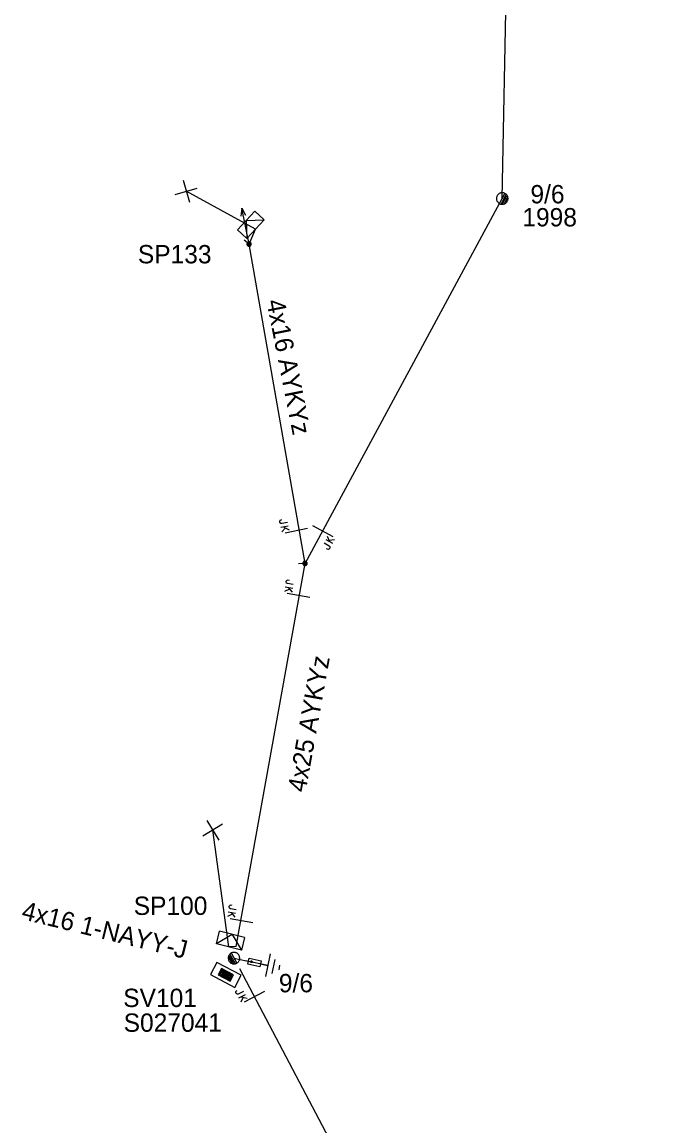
# Model space of a CAD drawing. Extents: x -788458 to -786145, y -1154772 to -1152372.
# Drawn here: x -786434.1 to -786399.7, y -1153357 to -1153296.8 of the extents above; entities that cross this region are included whole.
import ezdxf

# ---------------------------------------------------------------- set-up
doc = ezdxf.new("R2010")
doc.units = 0
for name, color, linetype in [('Vrstva 1', 7, 'Continuous'), ('Vrstva 12', 7, 'Continuous'), ('Vrstva 13', 7, 'Continuous'), ('Vrstva 14', 7, 'Continuous'), ('Vrstva 15', 7, 'Continuous'), ('Vrstva 16', 7, 'Continuous'), ('Vrstva 18', 7, 'Continuous'), ('Vrstva 2', 7, 'Continuous'), ('Vrstva 28', 7, 'Continuous'), ('Vrstva 29', 7, 'Continuous'), ('Vrstva 30', 7, 'Continuous'), ('Vrstva 31', 7, 'Continuous'), ('Vrstva 33', 7, 'Continuous'), ('Vrstva 34', 7, 'Continuous'), ('Vrstva 52', 7, 'Continuous'), ('Vrstva 53', 7, 'Continuous'), ('Vrstva 54', 7, 'Continuous'), ('Vrstva 55', 7, 'Continuous'), ('Vrstva 59', 7, 'Continuous'), ('Vrstva 8', 7, 'Continuous'), ('Vrstva 9', 7, 'Continuous')]:
    doc.layers.add(name, color=color, linetype=linetype)

# ---------------------------------------------------------------- blocks, each defined once
blk = doc.blocks.new('NN440')
at = {"layer": 'Vrstva 2'}
for points in [[(0.63, 0), (0.63, 0.06), (0.62, 0.13), (0.6, 0.19), (0.58, 0.25), (0.55, 0.31), (0.51, 0.37), (0.47, 0.42), (0.42, 0.46), (0.37, 0.51), (0.32, 0.54), (0.26, 0.57), (0.2, 0.59), (0.13, 0.61), (0.07, 0.62), (0, 0.63), (-0.06, 0.62), (-0.13, 0.61), (-0.19, 0.59), (-0.26, 0.57), (-0.31, 0.54), (-0.37, 0.51), (-0.42, 0.46), (-0.47, 0.42), (-0.51, 0.37), (-0.54, 0.31), (-0.57, 0.25), (-0.6, 0.19), (-0.62, 0.13), (-0.63, 0.06), (-0.63, 0), (-0.63, -0.07), (-0.62, -0.14), (-0.6, -0.2), (-0.57, -0.26), (-0.54, -0.32), (-0.51, -0.37), (-0.47, -0.43), (-0.42, -0.47), (-0.37, -0.51), (-0.31, -0.55), (-0.26, -0.58), (-0.19, -0.6), (-0.13, -0.62), (-0.06, -0.63), (0, -0.63), (0.07, -0.63), (0.13, -0.62), (0.2, -0.6), (0.26, -0.58), (0.32, -0.55), (0.37, -0.51), (0.42, -0.47), (0.47, -0.43), (0.51, -0.37), (0.55, -0.32), (0.58, -0.26), (0.6, -0.2), (0.62, -0.14), (0.63, -0.07), (0.63, 0)], [(-0.63, 0), (0.63, 0)], [(-0.6, -0.18), (0.57, -0.18)], [(-0.51, -0.32), (0.5, -0.32)], [(-0.37, -0.47), (0.35, -0.47)]]:
    blk.add_lwpolyline(points, dxfattribs=at)
blk = doc.blocks.new('NN560')
at = {"layer": 'Vrstva 2'}
for points in [[(1.999, -0.001), (1.59, 0.141)], [(0, -0.001), (1.999, -0.001)], [(1.999, -0.001), (1.59, -0.134)]]:
    blk.add_lwpolyline(points, dxfattribs=at)
blk = doc.blocks.new('NN840')
at = {"layer": 'Vrstva 15'}
for points in [[(0.003, 0.619), (0.003, -0.631)], [(-0.538, -0.385), (-0.538, -0.71)], [(-0.332, -0.385), (-0.332, -0.798)], [(-0.332, -0.641), (-0.125, -0.385)], [(-0.263, -0.557), (-0.091, -0.798)], [(-0.745, -0.71), (-0.745, -0.66)], [(-0.73, -0.764), (-0.745, -0.71)], [(-0.657, -0.798), (-0.73, -0.764)], [(-0.627, -0.798), (-0.657, -0.798)], [(-0.558, -0.764), (-0.627, -0.798)], [(-0.538, -0.71), (-0.558, -0.764)]]:
    blk.add_lwpolyline(points, dxfattribs=at)
blk = doc.blocks.new('NN800')
at = {"layer": 'Vrstva 1'}
for points in [[(-0.442, 0.442), (0.442, -0.442)], [(-0.442, -0.442), (0.442, 0.442)]]:
    blk.add_lwpolyline(points, dxfattribs=at)
blk = doc.blocks.new('NN820')
at = {"layer": 'Vrstva 13'}
for points in [[(-0.003, 0.004), (-0.003, -1.049)], [(-0.165, -0.813), (0.165, -0.813)], [(-0.165, -1.473), (-0.165, -0.813)], [(-0.003, -1.049), (-0.062, -0.926)], [(-0.003, -1.049), (0.057, -0.926)], [(0.165, -0.813), (0.165, -1.473)], [(0.165, -1.473), (-0.165, -1.473)], [(-0.003, -1.473), (-0.003, -1.871)]]:
    blk.add_lwpolyline(points, dxfattribs=at)
blk = doc.blocks.new('NN620')
at = {"layer": 'Vrstva 8'}
for points in [[(0.752, 0.004), (-0.748, 0.004)], [(-0.748, 0.004), (-0.748, -0.746)], [(0.752, -0.746), (0.752, 0.004)], [(0.368, -0.18), (-0.376, -0.18)], [(-0.376, -0.18), (-0.376, -0.558)], [(-0.376, -0.558), (0.368, -0.558)], [(0.321, -0.227), (-0.329, -0.227)], [(-0.329, -0.227), (-0.329, -0.51)], [(-0.329, -0.51), (0.321, -0.51)], [(0.274, -0.274), (-0.281, -0.274)], [(-0.281, -0.274), (-0.281, -0.463)], [(-0.281, -0.463), (0.274, -0.463)], [(0.227, -0.321), (-0.234, -0.321)], [(-0.234, -0.321), (-0.234, -0.416)], [(-0.234, -0.416), (0.227, -0.416)], [(-0.193, -0.369), (0.185, -0.369)], [(0.227, -0.416), (0.227, -0.321)], [(0.274, -0.463), (0.274, -0.274)], [(0.321, -0.51), (0.321, -0.227)], [(0.368, -0.558), (0.368, -0.18)], [(-0.748, -0.746), (0.752, -0.746)]]:
    blk.add_lwpolyline(points, dxfattribs=at)
blk = doc.blocks.new('NN630')
at = {"layer": 'Vrstva 9'}
for points in [[(-0.003, -0.7), (-0.703, 0)], [(-0.703, -0.7), (-0.703, 0), (0.697, 0), (0.697, -0.7)], [(-0.003, -0.7), (0.697, 0)], [(-0.703, -0.7), (0.697, -0.7)]]:
    blk.add_lwpolyline(points, dxfattribs=at)
blk = doc.blocks.new('NN810')
at = {"layer": 'Vrstva 14'}
for points in [[(0.004, -0.64), (0.004, -1.89)], [(0.629, -1.89), (-0.621, -1.89)], [(0.388, -2.2), (-0.399, -2.2)], [(0.004, -2.515), (-0.124, -2.515)], [(0.137, -2.515), (0.004, -2.515)]]:
    blk.add_lwpolyline(points, dxfattribs=at)
blk = doc.blocks.new('NN500')
at = {"layer": 'Vrstva 2'}
for points in [[(0, -0.24), (0.02, -0.23), (0.05, -0.23), (0.07, -0.22), (0.09, -0.22), (0.12, -0.2), (0.14, -0.19), (0.16, -0.18), (0.17, -0.16), (0.19, -0.14), (0.2, -0.12), (0.21, -0.1), (0.22, -0.07), (0.23, -0.05), (0.23, -0.02), (0.23, 0), (0.23, 0.02), (0.23, 0.05), (0.22, 0.07), (0.21, 0.1), (0.2, 0.12), (0.19, 0.14), (0.17, 0.16), (0.16, 0.17), (0.14, 0.19), (0.12, 0.2), (0.09, 0.21), (0.07, 0.22), (0.05, 0.23), (0.02, 0.23), (0, 0.23), (-0.03, 0.23), (-0.05, 0.23), (-0.07, 0.22), (-0.1, 0.21), (-0.12, 0.2), (-0.14, 0.19), (-0.16, 0.17), (-0.18, 0.16), (-0.19, 0.14), (-0.2, 0.12), (-0.22, 0.1), (-0.22, 0.07), (-0.23, 0.05), (-0.23, 0.02), (-0.24, 0), (-0.23, -0.02), (-0.23, -0.05), (-0.22, -0.07), (-0.22, -0.1), (-0.2, -0.12), (-0.19, -0.14), (-0.18, -0.16), (-0.16, -0.18), (-0.14, -0.19), (-0.12, -0.2), (-0.1, -0.22), (-0.07, -0.22), (-0.05, -0.23), (-0.03, -0.23), (0, -0.24)], [(0, -0.24), (0.02, -0.23), (0.05, -0.23), (0.07, -0.22), (0.09, -0.22), (0.12, -0.2), (0.14, -0.19), (0.16, -0.18), (0.17, -0.16), (0.19, -0.14), (0.2, -0.12), (0.21, -0.1), (0.22, -0.07), (0.23, -0.05), (0.23, -0.02), (0.23, 0), (0.23, 0.02), (0.23, 0.05), (0.22, 0.07), (0.21, 0.1), (0.2, 0.12), (0.19, 0.14), (0.17, 0.16), (0.16, 0.17), (0.14, 0.19), (0.12, 0.2), (0.09, 0.21), (0.07, 0.22), (0.05, 0.23), (0.02, 0.23), (0, 0.23), (-0.03, 0.23), (-0.05, 0.23), (-0.07, 0.22), (-0.1, 0.21), (-0.12, 0.2), (-0.14, 0.19), (-0.16, 0.17), (-0.18, 0.16), (-0.19, 0.14), (-0.2, 0.12), (-0.22, 0.1), (-0.22, 0.07), (-0.23, 0.05), (-0.23, 0.02), (-0.24, 0), (-0.23, -0.02), (-0.23, -0.05), (-0.22, -0.07), (-0.22, -0.1), (-0.2, -0.12), (-0.19, -0.14), (-0.18, -0.16), (-0.16, -0.18), (-0.14, -0.19), (-0.12, -0.2), (-0.1, -0.22), (-0.07, -0.22), (-0.05, -0.23), (-0.03, -0.23), (0, -0.24)], [(0, -0.21), (0.02, -0.2), (0.04, -0.2), (0.06, -0.2), (0.08, -0.19), (0.1, -0.18), (0.12, -0.17), (0.14, -0.15), (0.15, -0.14), (0.16, -0.12), (0.18, -0.1), (0.19, -0.08), (0.19, -0.06), (0.2, -0.04), (0.2, -0.02), (0.2, 0), (0.2, 0.02), (0.2, 0.04), (0.19, 0.06), (0.19, 0.08), (0.18, 0.1), (0.16, 0.12), (0.15, 0.14), (0.14, 0.15), (0.12, 0.17), (0.1, 0.18), (0.08, 0.19), (0.06, 0.19), (0.04, 0.2), (0.02, 0.2), (0, 0.2), (-0.02, 0.2), (-0.04, 0.2), (-0.06, 0.19), (-0.08, 0.19), (-0.1, 0.18), (-0.12, 0.17), (-0.14, 0.15), (-0.15, 0.14), (-0.17, 0.12), (-0.18, 0.1), (-0.19, 0.08), (-0.2, 0.06), (-0.2, 0.04), (-0.21, 0.02), (-0.21, 0), (-0.21, -0.02), (-0.2, -0.04), (-0.2, -0.06), (-0.19, -0.08), (-0.18, -0.1), (-0.17, -0.12), (-0.15, -0.14), (-0.14, -0.15), (-0.12, -0.17), (-0.1, -0.18), (-0.08, -0.19), (-0.06, -0.2), (-0.04, -0.2), (-0.02, -0.2), (0, -0.21)], [(0, -0.18), (0.02, -0.18), (0.04, -0.17), (0.05, -0.17), (0.07, -0.16), (0.09, -0.15), (0.1, -0.14), (0.12, -0.13), (0.13, -0.12), (0.14, -0.1), (0.15, -0.09), (0.16, -0.07), (0.17, -0.05), (0.17, -0.04), (0.17, -0.02), (0.17, 0), (0.17, 0.02), (0.17, 0.04), (0.17, 0.05), (0.16, 0.07), (0.15, 0.09), (0.14, 0.1), (0.13, 0.12), (0.12, 0.13), (0.1, 0.14), (0.09, 0.15), (0.07, 0.16), (0.05, 0.17), (0.04, 0.17), (0.02, 0.17), (0, 0.18), (-0.02, 0.17), (-0.04, 0.17), (-0.06, 0.17), (-0.07, 0.16), (-0.09, 0.15), (-0.1, 0.14), (-0.12, 0.13), (-0.13, 0.12), (-0.14, 0.1), (-0.15, 0.09), (-0.16, 0.07), (-0.17, 0.05), (-0.17, 0.04), (-0.18, 0.02), (-0.18, 0), (-0.18, -0.02), (-0.17, -0.04), (-0.17, -0.05), (-0.16, -0.07), (-0.15, -0.09), (-0.14, -0.1), (-0.13, -0.12), (-0.12, -0.13), (-0.1, -0.14), (-0.09, -0.15), (-0.07, -0.16), (-0.06, -0.17), (-0.04, -0.17), (-0.02, -0.18), (0, -0.18)], [(0, -0.15), (0.01, -0.15), (0.03, -0.14), (0.04, -0.14), (0.06, -0.13), (0.07, -0.13), (0.08, -0.12), (0.1, -0.11), (0.11, -0.1), (0.12, -0.09), (0.13, -0.07), (0.13, -0.06), (0.14, -0.05), (0.14, -0.03), (0.14, -0.02), (0.14, 0), (0.14, 0.01), (0.14, 0.03), (0.14, 0.04), (0.13, 0.06), (0.13, 0.07), (0.12, 0.09), (0.11, 0.1), (0.1, 0.11), (0.08, 0.12), (0.07, 0.13), (0.06, 0.13), (0.04, 0.14), (0.03, 0.14), (0.01, 0.14), (0, 0.15), (-0.02, 0.14), (-0.03, 0.14), (-0.05, 0.14), (-0.06, 0.13), (-0.07, 0.13), (-0.09, 0.12), (-0.1, 0.11), (-0.11, 0.1), (-0.12, 0.09), (-0.13, 0.07), (-0.13, 0.06), (-0.14, 0.04), (-0.14, 0.03), (-0.15, 0.01), (-0.15, 0), (-0.15, -0.02), (-0.14, -0.03), (-0.14, -0.05), (-0.13, -0.06), (-0.13, -0.07), (-0.12, -0.09), (-0.11, -0.1), (-0.1, -0.11), (-0.09, -0.12), (-0.07, -0.13), (-0.06, -0.13), (-0.05, -0.14), (-0.03, -0.14), (-0.02, -0.15), (0, -0.15)], [(0, -0.12), (0.01, -0.12), (0.02, -0.11), (0.03, -0.11), (0.05, -0.11), (0.06, -0.1), (0.07, -0.09), (0.08, -0.09), (0.09, -0.08), (0.09, -0.07), (0.1, -0.06), (0.11, -0.05), (0.11, -0.04), (0.11, -0.02), (0.11, -0.01), (0.12, 0), (0.11, 0.01), (0.11, 0.02), (0.11, 0.04), (0.11, 0.05), (0.1, 0.06), (0.09, 0.07), (0.09, 0.08), (0.08, 0.09), (0.07, 0.09), (0.06, 0.1), (0.05, 0.11), (0.03, 0.11), (0.02, 0.11), (0.01, 0.12), (0, 0.12), (-0.01, 0.12), (-0.03, 0.11), (-0.04, 0.11), (-0.05, 0.11), (-0.06, 0.1), (-0.07, 0.09), (-0.08, 0.09), (-0.09, 0.08), (-0.1, 0.07), (-0.1, 0.06), (-0.11, 0.05), (-0.11, 0.04), (-0.12, 0.02), (-0.12, 0.01), (-0.12, 0), (-0.12, -0.01), (-0.12, -0.02), (-0.11, -0.04), (-0.11, -0.05), (-0.1, -0.06), (-0.1, -0.07), (-0.09, -0.08), (-0.08, -0.09), (-0.07, -0.09), (-0.06, -0.1), (-0.05, -0.11), (-0.04, -0.11), (-0.03, -0.11), (-0.01, -0.12), (0, -0.12)], [(0, -0.09), (0.01, -0.09), (0.02, -0.09), (0.03, -0.08), (0.03, -0.08), (0.04, -0.08), (0.05, -0.07), (0.06, -0.07), (0.06, -0.06), (0.07, -0.05), (0.07, -0.04), (0.08, -0.04), (0.08, -0.03), (0.08, -0.02), (0.09, -0.01), (0.09, 0), (0.09, 0.01), (0.08, 0.02), (0.08, 0.03), (0.08, 0.03), (0.07, 0.04), (0.07, 0.05), (0.06, 0.06), (0.06, 0.06), (0.05, 0.07), (0.04, 0.07), (0.03, 0.08), (0.03, 0.08), (0.02, 0.08), (0.01, 0.09), (0, 0.09), (-0.01, 0.09), (-0.02, 0.08), (-0.03, 0.08), (-0.04, 0.08), (-0.04, 0.07), (-0.05, 0.07), (-0.06, 0.06), (-0.07, 0.06), (-0.07, 0.05), (-0.08, 0.04), (-0.08, 0.03), (-0.08, 0.03), (-0.09, 0.02), (-0.09, 0.01), (-0.09, 0), (-0.09, -0.01), (-0.09, -0.02), (-0.08, -0.03), (-0.08, -0.04), (-0.08, -0.04), (-0.07, -0.05), (-0.07, -0.06), (-0.06, -0.07), (-0.05, -0.07), (-0.04, -0.08), (-0.04, -0.08), (-0.03, -0.08), (-0.02, -0.09), (-0.01, -0.09), (0, -0.09)], [(0, -0.06), (0, -0.06), (0.01, -0.06), (0.02, -0.05), (0.02, -0.05), (0.03, -0.05), (0.03, -0.05), (0.04, -0.04), (0.04, -0.04), (0.05, -0.03), (0.05, -0.03), (0.05, -0.02), (0.05, -0.02), (0.05, -0.01), (0.06, -0.01), (0.06, 0), (0.06, 0.01), (0.05, 0.01), (0.05, 0.02), (0.05, 0.02), (0.05, 0.03), (0.05, 0.03), (0.04, 0.04), (0.04, 0.04), (0.03, 0.05), (0.03, 0.05), (0.02, 0.05), (0.02, 0.05), (0.01, 0.06), (0, 0.06), (0, 0.06), (-0.01, 0.06), (-0.01, 0.06), (-0.02, 0.05), (-0.02, 0.05), (-0.03, 0.05), (-0.03, 0.05), (-0.04, 0.04), (-0.04, 0.04), (-0.05, 0.03), (-0.05, 0.03), (-0.05, 0.02), (-0.06, 0.02), (-0.06, 0.01), (-0.06, 0.01), (-0.06, 0), (-0.06, -0.01), (-0.06, -0.01), (-0.06, -0.02), (-0.05, -0.02), (-0.05, -0.03), (-0.05, -0.03), (-0.04, -0.04), (-0.04, -0.04), (-0.03, -0.05), (-0.03, -0.05), (-0.02, -0.05), (-0.02, -0.05), (-0.01, -0.06), (-0.01, -0.06), (0, -0.06)], [(0, -0.03), (0, -0.03), (0, -0.03), (0.01, -0.03), (0.01, -0.03), (0.01, -0.02), (0.02, -0.02), (0.02, -0.02), (0.02, -0.02), (0.02, -0.02), (0.02, -0.01), (0.02, -0.01), (0.03, -0.01), (0.03, -0.01), (0.03, 0), (0.03, 0), (0.03, 0), (0.03, 0.01), (0.03, 0.01), (0.02, 0.01), (0.02, 0.01), (0.02, 0.02), (0.02, 0.02), (0.02, 0.02), (0.02, 0.02), (0.01, 0.02), (0.01, 0.02), (0.01, 0.03), (0, 0.03), (0, 0.03), (0, 0.03), (0, 0.03), (-0.01, 0.03), (-0.01, 0.03), (-0.01, 0.02), (-0.02, 0.02), (-0.02, 0.02), (-0.02, 0.02), (-0.02, 0.02), (-0.02, 0.02), (-0.03, 0.01), (-0.03, 0.01), (-0.03, 0.01), (-0.03, 0.01), (-0.03, 0), (-0.03, 0), (-0.03, 0), (-0.03, -0.01), (-0.03, -0.01), (-0.03, -0.01), (-0.03, -0.01), (-0.02, -0.02), (-0.02, -0.02), (-0.02, -0.02), (-0.02, -0.02), (-0.02, -0.02), (-0.01, -0.03), (-0.01, -0.03), (-0.01, -0.03), (0, -0.03), (0, -0.03)], [(0.23, 0), (0.7, 0)]]:
    blk.add_lwpolyline(points, dxfattribs=at)

msp = doc.modelspace()

# ---------------------------------------------------------------- linework, layer by layer
at = {"layer": 'Vrstva 1'}
msp.add_lwpolyline([(-786409.44, -1153372.75), (-786422.249, -1153348.421)], dxfattribs=at)
at = {"layer": 'Vrstva 52'}
for points in [[(-786418.69, -1153326.31), (-786407.94, -1153306.41), (-786407.23, -1153270.29), (-786403.165, -1153233.535), (-786401.149, -1153233.144), (-786399.719, -1153232.1), (-786399.67, -1153231.94)], [(-786422.445, -1153347.191), (-786418.69, -1153326.31)]]:
    msp.add_lwpolyline(points, dxfattribs=at)
at = {"layer": 'Vrstva 54'}
msp.add_lwpolyline([(-786418.69, -1153326.31), (-786421.74, -1153308.9), (-786421.39, -1153308.09)], dxfattribs=at)
at = {"layer": 'Vrstva 59'}
for points in [[(-786421.39, -1153308.09), (-786425.16, -1153306.02)], [(-786422.84, -1153347.22), (-786423.72, -1153340.86)]]:
    msp.add_lwpolyline(points, dxfattribs=at)
at = {"layer": 'Vrstva 8'}
msp.add_lwpolyline([(-786422.445, -1153347.191), (-786422.84, -1153347.22)], dxfattribs=at)

# ---------------------------------------------------------------- block references
at = {"layer": 'Vrstva 13'}
for name, p, xscale, yscale, rotation in [('NN440', (-786407.94, -1153306.41), 0.5, 0.5, 61.25196383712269), ('NN500', (-786421.74, -1153308.9), 0.5, 0.5, 141.45899997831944), ('NN500', (-786418.69, -1153326.31), 0.5, 0.49999999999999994, -176.05599994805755), ('NN440', (-786422.56, -1153347.83), 0.49999999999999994, 0.5, -61.81187780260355)]:
    msp.add_blockref(name, p, dxfattribs=dict(at, xscale=xscale, yscale=yscale, rotation=rotation))
at = {"layer": 'Vrstva 13', "rotation": 101.5531389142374}
msp.add_blockref('NN560', (-786421.74, -1153308.9), dxfattribs=at)
at = {"layer": 'Vrstva 15', "rotation": 78.03681805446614}
msp.add_blockref('NN810', (-786422.56, -1153347.83), dxfattribs=at)
at = {"layer": 'Vrstva 16', "rotation": 77.67801340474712}
msp.add_blockref('NN820', (-786422.56, -1153347.83), dxfattribs=at)
at = {"layer": 'Vrstva 18'}
for p, rotation in [((-786419.157, -1153324.527), -78.81098889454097), ((-786417.733, -1153324.539), 61.251602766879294), ((-786419.04, -1153328.065), -99.89796668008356), ((-786422.149, -1153345.789), -99.9451222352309), ((-786421.448, -1153349.941), -62.23387910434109)]:
    msp.add_blockref('NN840', p, dxfattribs=dict(at, rotation=rotation))
at = {"layer": 'Vrstva 28', "rotation": -27.71081365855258}
msp.add_blockref('NN620', (-786422.832, -1153348.421), dxfattribs=at)
at = {"layer": 'Vrstva 31'}
for p, rotation in [((-786421.39, -1153308.09), -133.318991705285), ((-786422.84, -1153347.22), 165.68517305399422)]:
    msp.add_blockref('NN630', p, dxfattribs=dict(at, rotation=rotation))
at = {"layer": 'Vrstva 34'}
for p, rotation in [((-786425.16, -1153306.02), -28.770011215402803), ((-786423.72, -1153340.86), -103.28500827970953)]:
    msp.add_blockref('NN800', p, dxfattribs=dict(at, rotation=rotation))

# ---------------------------------------------------------------- texts
at = {"layer": 'Vrstva 12'}
for p in [(-786406.401, -1153306.678), (-786420.115, -1153349.695)]:
    msp.add_text('9/6', height=1, dxfattribs=at).set_placement(p)
at = {"layer": 'Vrstva 14'}
msp.add_text('1998', height=1, dxfattribs=at).set_placement((-786406.841, -1153307.935))
at = {"layer": 'Vrstva 29'}
msp.add_text('S027041', height=1, dxfattribs=at).set_placement((-786428.575, -1153351.85))
at = {"layer": 'Vrstva 30'}
msp.add_text('SV101', height=1, dxfattribs=at).set_placement((-786428.598, -1153350.498))
at = {"layer": 'Vrstva 33'}
for s, p in [('SP133', (-786427.8, -1153309.95)), ('SP100', (-786428.025, -1153345.477))]:
    msp.add_text(s, height=1, dxfattribs=at).set_placement(p)
at = {"layer": 'Vrstva 53'}
msp.add_text('4x25 AYKYz', height=1, rotation=79.805, dxfattribs=at).set_placement((-786418.66, -1153338.829))
at = {"layer": 'Vrstva 55'}
for s, rotation, p in [('4x16 AYKYz', 281.189, (-786420.8, -1153312.007)), ('4x16 1-NAYY-J', 346.283, (-786434.196, -1153345.692))]:
    msp.add_text(s, height=1, rotation=rotation, dxfattribs=at).set_placement(p)

doc.saveas('drawing.dxf')
